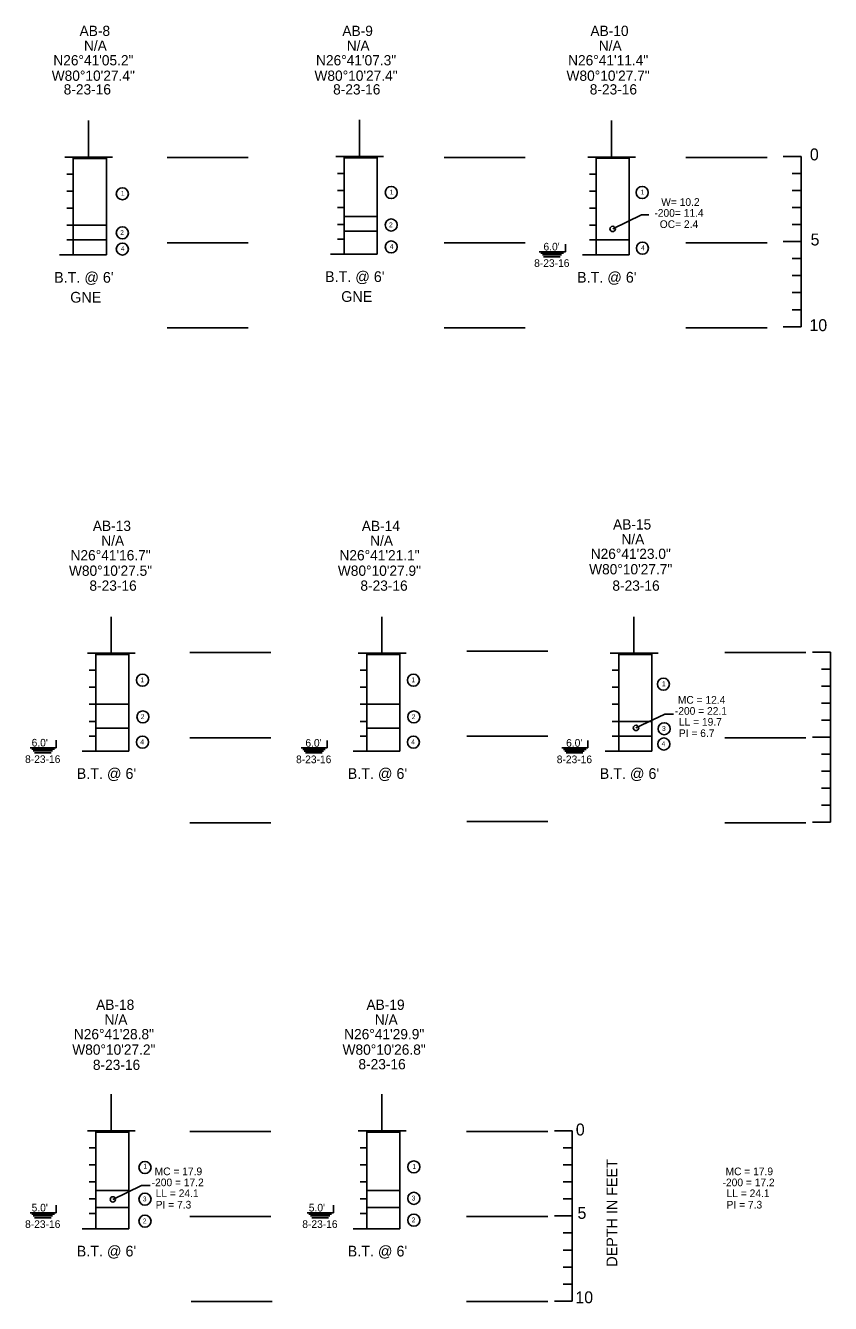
# Model space of a CAD drawing. Extents: x 0 to 331, y -72 to 117.
# Drawn here: x 93.6 to 118.94, y -21.85 to 18.38 of the extents above; entities that cross this region are included whole.
import ezdxf

# ---------------------------------------------------------------- set-up
doc = ezdxf.new("R2010")
doc.units = 0
for name, color, linetype in [('1-BORE', 7, 'Continuous'), ('1-GRID', 7, 'Continuous'), ('1-TEXT', 7, 'Continuous')]:
    doc.layers.add(name, color=color, linetype=linetype)

msp = doc.modelspace()

# ---------------------------------------------------------------- linework, layer by layer
at = {"layer": '1-BORE'}
for p, q in [((95.097, 14.2), (96.142, 14.2)), ((103.629, 14.222), (104.674, 14.222)), ((111.565, 14.202), (112.61, 14.202)), ((95.097, 12.097), (96.142, 12.097)), ((95.097, 12.097), (96.142, 12.097)), ((103.629, 12.369), (104.674, 12.369)), ((103.629, 12.369), (104.674, 12.369)), ((112.089, 11.986), (112.993, 12.426)), ((112.993, 12.426), (113.221, 12.426)), ((103.629, 11.906), (104.674, 11.906)), ((103.629, 11.906), (104.674, 11.906)), ((95.097, 11.634), (96.142, 11.634)), ((95.097, 11.634), (96.142, 11.634)), ((111.565, 11.637), (112.61, 11.637)), ((111.565, 11.637), (112.61, 11.637)), ((95.097, 11.16), (94.669, 11.16)), ((95.097, 11.16), (96.142, 11.16)), ((103.629, 11.183), (103.201, 11.183)), ((103.629, 11.183), (104.674, 11.183)), ((111.565, 11.163), (111.137, 11.163)), ((111.565, 11.163), (112.61, 11.163)), ((95.809, -1.422), (96.854, -1.422)), ((104.342, -1.422), (105.387, -1.422)), ((112.278, -1.422), (113.323, -1.422)), ((95.809, -2.989), (96.854, -2.989)), ((95.809, -2.989), (96.854, -2.989)), ((104.342, -2.989), (105.387, -2.989)), ((104.342, -2.989), (105.387, -2.989)), ((112.278, -3.525), (113.323, -3.525)), ((112.278, -3.525), (113.323, -3.525)), ((112.82, -3.734), (113.724, -3.294)), ((113.724, -3.294), (114, -3.294)), ((95.809, -3.739), (96.854, -3.739)), ((95.809, -3.739), (96.854, -3.739)), ((104.342, -3.739), (105.387, -3.739)), ((104.342, -3.739), (105.387, -3.739)), ((112.278, -3.988), (113.323, -3.988)), ((112.278, -3.988), (113.323, -3.988)), ((95.809, -4.462), (95.381, -4.462)), ((95.809, -4.462), (96.854, -4.462)), ((104.342, -4.462), (103.913, -4.462)), ((104.342, -4.462), (105.387, -4.462)), ((112.278, -4.462), (111.849, -4.462)), ((112.278, -4.462), (113.323, -4.462)), ((95.809, -16.459), (96.854, -16.459)), ((104.342, -16.459), (105.387, -16.459)), ((95.809, -18.3), (96.854, -18.3)), ((95.809, -18.3), (96.854, -18.3)), ((96.344, -18.578), (97.247, -18.139)), ((97.247, -18.139), (97.524, -18.138)), ((104.341, -18.3), (105.386, -18.3)), ((104.342, -18.3), (105.387, -18.3)), ((95.809, -18.836), (96.854, -18.836)), ((95.809, -18.836), (96.854, -18.836)), ((104.341, -18.836), (105.386, -18.836)), ((104.342, -18.836), (105.387, -18.836)), ((95.809, -19.498), (95.381, -19.498)), ((95.809, -19.498), (96.854, -19.498)), ((104.342, -19.498), (103.913, -19.498)), ((104.342, -19.498), (105.387, -19.498))]:
    msp.add_line(p, q, dxfattribs=at)
for points in [[(96.142, 14.2), (96.142, 14.241), (95.097, 14.241), (95.097, 14.2), (96.142, 14.2), (96.142, 14.2)], [(96.142, 11.16), (96.142, 14.241), (95.097, 14.241), (95.097, 11.16)], [(104.674, 14.222), (104.674, 14.263), (103.629, 14.263), (103.629, 14.222), (104.674, 14.222), (104.674, 14.222)], [(104.674, 11.183), (104.674, 14.263), (103.629, 14.263), (103.629, 11.183)], [(112.61, 14.202), (112.61, 14.243), (111.565, 14.243), (111.565, 14.202), (112.61, 14.202), (112.61, 14.202)], [(112.61, 11.163), (112.61, 14.243), (111.565, 14.243), (111.565, 11.163)], [(96.854, -4.462), (96.854, -1.381), (95.809, -1.381), (95.809, -4.462)], [(96.854, -1.422), (96.854, -1.381), (95.809, -1.381), (95.809, -1.422), (96.854, -1.422), (96.854, -1.422)], [(105.387, -4.462), (105.387, -1.381), (104.342, -1.381), (104.342, -4.462)], [(105.387, -1.422), (105.387, -1.381), (104.342, -1.381), (104.342, -1.422), (105.387, -1.422), (105.387, -1.422)], [(113.323, -4.462), (113.323, -1.381), (112.278, -1.381), (112.278, -4.462)], [(113.323, -1.422), (113.323, -1.381), (112.278, -1.381), (112.278, -1.422), (113.323, -1.422), (113.323, -1.422)], [(96.854, -19.498), (96.854, -16.418), (95.809, -16.418), (95.809, -19.498)], [(96.854, -16.459), (96.854, -16.418), (95.809, -16.418), (95.809, -16.459), (96.854, -16.459), (96.854, -16.459)], [(105.387, -19.498), (105.387, -16.418), (104.342, -16.418), (104.342, -19.498)], [(105.387, -16.459), (105.387, -16.418), (104.342, -16.418), (104.342, -16.459), (105.387, -16.459), (105.387, -16.459)]]:
    msp.add_lwpolyline(points, dxfattribs=at)
for centre, start, end in [((112.086, 11.979), 0, 180), ((112.086, 11.979), 180, 0), ((112.821, -3.732), 0, 180), ((112.821, -3.732), 180, 0), ((96.345, -18.576), 0, 180), ((96.345, -18.576), 180, 0)]:
    msp.add_arc(centre, 0.0848, start, end, dxfattribs=at)
at = {"layer": '1-GRID'}
for p, q in [((98.056, 14.223), (100.609, 14.223)), ((106.777, 14.223), (109.331, 14.223)), ((114.393, 14.223), (116.947, 14.223)), ((118.019, 14.259), (117.454, 14.259)), ((94.892, 13.705), (95.097, 13.705)), ((103.425, 13.728), (103.629, 13.728)), ((111.361, 13.708), (111.565, 13.708)), ((118.019, 13.724), (117.733, 13.724)), ((94.892, 13.169), (95.097, 13.169)), ((103.425, 13.192), (103.629, 13.192)), ((111.361, 13.172), (111.565, 13.172)), ((118.019, 13.188), (117.733, 13.188)), ((94.892, 12.633), (95.097, 12.633)), ((103.425, 12.656), (103.629, 12.656)), ((111.361, 12.636), (111.565, 12.636)), ((118.019, 12.652), (117.733, 12.652)), ((94.892, 12.097), (95.097, 12.097)), ((103.425, 12.12), (103.629, 12.12)), ((111.361, 12.1), (111.565, 12.1)), ((118.019, 12.116), (117.733, 12.116)), ((94.892, 11.634), (95.097, 11.634)), ((98.056, 11.543), (100.609, 11.543)), ((103.425, 11.657), (103.629, 11.657)), ((106.777, 11.543), (109.331, 11.543)), ((111.361, 11.637), (111.565, 11.637)), ((114.393, 11.543), (116.947, 11.543)), ((118.019, 11.58), (117.454, 11.58)), ((118.019, 11.58), (117.454, 11.58)), ((95.097, 11.16), (95.302, 11.16)), ((103.629, 11.183), (103.834, 11.183)), ((111.565, 11.163), (111.77, 11.163)), ((118.019, 11.044), (117.733, 11.044)), ((118.019, 10.508), (117.733, 10.508)), ((118.019, 9.973), (117.733, 9.973)), ((118.019, 9.437), (117.733, 9.437)), ((98.056, 8.864), (100.609, 8.864)), ((106.777, 8.864), (109.331, 8.864)), ((114.393, 8.864), (116.947, 8.864)), ((118.019, 8.901), (117.454, 8.901)), ((98.771, -1.362), (101.325, -1.362)), ((107.49, -1.317), (110.043, -1.317)), ((115.615, -1.362), (118.169, -1.362)), ((118.944, -1.344), (118.379, -1.344)), ((118.944, -1.344), (118.379, -1.344)), ((95.604, -1.917), (95.809, -1.917)), ((104.137, -1.917), (104.342, -1.917)), ((112.073, -1.917), (112.278, -1.917)), ((118.944, -1.88), (118.658, -1.88)), ((95.604, -2.453), (95.809, -2.453)), ((104.137, -2.453), (104.342, -2.453)), ((112.073, -2.453), (112.278, -2.453)), ((118.944, -2.416), (118.658, -2.416)), ((95.604, -2.989), (95.809, -2.989)), ((104.137, -2.989), (104.342, -2.989)), ((112.073, -2.989), (112.278, -2.989)), ((118.944, -2.952), (118.658, -2.952)), ((95.604, -3.525), (95.809, -3.525)), ((104.137, -3.525), (104.342, -3.525)), ((112.073, -3.525), (112.278, -3.525)), ((118.944, -3.487), (118.658, -3.487)), ((95.604, -3.988), (95.809, -3.988)), ((104.137, -3.988), (104.342, -3.988)), ((107.49, -3.996), (110.043, -3.996)), ((112.073, -3.988), (112.278, -3.988)), ((118.944, -4.023), (118.379, -4.023)), ((118.944, -4.023), (118.379, -4.023)), ((98.771, -4.042), (101.325, -4.042)), ((115.615, -4.042), (118.169, -4.042)), ((95.809, -4.462), (96.014, -4.462)), ((104.342, -4.462), (104.546, -4.462)), ((112.278, -4.462), (112.482, -4.462)), ((118.944, -4.559), (118.658, -4.559)), ((118.944, -5.095), (118.658, -5.095)), ((118.944, -5.631), (118.658, -5.631)), ((118.944, -6.167), (118.658, -6.167)), ((98.771, -6.721), (101.325, -6.721)), ((107.49, -6.675), (110.043, -6.675)), ((115.615, -6.721), (118.169, -6.721)), ((118.944, -6.703), (118.379, -6.703)), ((98.771, -16.438), (101.324, -16.438)), ((107.485, -16.439), (110.039, -16.439)), ((110.815, -16.419), (110.25, -16.419)), ((110.815, -16.419), (110.25, -16.419)), ((95.604, -16.954), (95.809, -16.954)), ((104.137, -16.954), (104.342, -16.954)), ((110.815, -16.955), (110.529, -16.955)), ((95.604, -17.489), (95.809, -17.489)), ((104.137, -17.489), (104.342, -17.489)), ((110.815, -17.491), (110.529, -17.491)), ((95.604, -18.025), (95.809, -18.025)), ((104.137, -18.025), (104.342, -18.025)), ((110.815, -18.026), (110.529, -18.026)), ((95.604, -18.561), (95.809, -18.561)), ((104.137, -18.561), (104.342, -18.561)), ((110.815, -18.562), (110.529, -18.562)), ((95.604, -19.024), (95.809, -19.024)), ((98.771, -19.117), (101.324, -19.117)), ((104.137, -19.024), (104.342, -19.024)), ((107.485, -19.118), (110.039, -19.118)), ((110.815, -19.098), (110.25, -19.098)), ((110.815, -19.098), (110.25, -19.098)), ((95.809, -19.498), (96.014, -19.498)), ((104.342, -19.498), (104.546, -19.498)), ((110.815, -19.634), (110.529, -19.634)), ((110.815, -20.17), (110.529, -20.17)), ((110.815, -20.706), (110.529, -20.706)), ((110.815, -21.242), (110.529, -21.242)), ((98.808, -21.796), (101.362, -21.796)), ((107.485, -21.796), (110.039, -21.796)), ((110.815, -21.777), (110.25, -21.777))]:
    msp.add_line(p, q, dxfattribs=at)
for points in [[(118.019, 11.58), (118.019, 14.259)], [(118.019, 8.901), (118.019, 11.58)], [(118.944, -4.023), (118.944, -1.344)], [(118.944, -6.703), (118.944, -4.023)], [(110.815, -19.098), (110.815, -16.419)], [(110.815, -21.777), (110.815, -19.098)]]:
    msp.add_lwpolyline(points, dxfattribs=at)
at = {"layer": '1-TEXT'}
for p, q in [((95.577, 15.392), (95.577, 14.241)), ((104.109, 15.414), (104.109, 14.263)), ((112.045, 15.394), (112.045, 14.243)), ((110.595, 11.262), (110.595, 11.497)), ((109.77, 11.262), (110.595, 11.262)), ((109.824, 11.213), (110.534, 11.213)), ((109.871, 11.164), (110.478, 11.164)), ((109.91, 11.105), (110.434, 11.105)), ((96.289, -0.23), (96.289, -1.381)), ((104.821, -0.23), (104.821, -1.381)), ((112.757, -0.23), (112.757, -1.381)), ((93.739, -4.356), (94.564, -4.356)), ((93.793, -4.405), (94.503, -4.405)), ((94.564, -4.356), (94.564, -4.121)), ((102.271, -4.363), (103.097, -4.363)), ((102.326, -4.412), (103.036, -4.412)), ((103.097, -4.363), (103.097, -4.127)), ((110.482, -4.363), (111.307, -4.363)), ((110.536, -4.412), (111.246, -4.412)), ((111.307, -4.363), (111.307, -4.127)), ((93.841, -4.454), (94.447, -4.454)), ((93.879, -4.513), (94.404, -4.513)), ((102.373, -4.461), (102.98, -4.461)), ((102.412, -4.52), (102.936, -4.52)), ((110.584, -4.461), (111.19, -4.461)), ((110.622, -4.52), (111.147, -4.52)), ((96.289, -15.267), (96.289, -16.418)), ((104.821, -15.267), (104.821, -16.418)), ((94.564, -18.996), (94.564, -18.76)), ((103.293, -18.996), (103.293, -18.76)), ((93.739, -18.996), (94.564, -18.996)), ((93.793, -19.045), (94.503, -19.045)), ((93.841, -19.094), (94.447, -19.094)), ((93.879, -19.153), (94.404, -19.153)), ((102.468, -18.996), (103.293, -18.996)), ((102.522, -19.045), (103.232, -19.045)), ((102.57, -19.094), (103.176, -19.094)), ((102.608, -19.153), (103.133, -19.153))]:
    msp.add_line(p, q, dxfattribs=at)
for points in [[(94.83, 14.241), (96.339, 14.241)], [(103.363, 14.263), (104.872, 14.263)], [(111.299, 14.243), (112.808, 14.243)], [(95.543, -1.381), (97.052, -1.381)], [(104.075, -1.381), (105.584, -1.381)], [(112.011, -1.381), (113.52, -1.381)], [(95.543, -16.418), (97.052, -16.418)], [(104.075, -16.418), (105.584, -16.418)]]:
    msp.add_lwpolyline(points, dxfattribs=at)
for centre in [(96.645, 13.087), (105.113, 13.127), (113.016, 13.127), (105.113, 12.103), (96.645, 11.856), (96.645, 11.346), (105.113, 11.412), (113.023, 11.373), (97.278, -2.23), (105.81, -2.23), (113.682, -2.356), (97.292, -3.385), (105.825, -3.385), (113.709, -3.757), (97.278, -4.179), (105.81, -4.179), (113.695, -4.239), (97.357, -17.571), (105.825, -17.554), (97.357, -18.57), (105.824, -18.543), (97.357, -19.262), (105.824, -19.229)]:
    msp.add_circle(centre, 0.19, dxfattribs=at)

# ---------------------------------------------------------------- texts
at = {"layer": '1-GRID'}
for s, height, p in [('0', 0.375, (118.296, 14.138)), ('5', 0.375, (118.319, 11.459)), ('10', 0.3751, (118.282, 8.762)), ('0', 0.375, (110.925, -16.563)), ('5', 0.375, (110.978, -19.189)), ('10', 0.3751, (110.911, -21.847))]:
    msp.add_text(s, height=height, dxfattribs=at).set_placement(p)
msp.add_text('DEPTH IN FEET', height=0.3376, rotation=90, dxfattribs=at).set_placement((112.23, -20.695))
at = {"layer": '1-TEXT'}
for s, height, p in [('AB-8', 0.3231, (95.298, 18.054)), ('AB-9', 0.3231, (103.573, 18.054)), ('AB-10', 0.3231, (111.385, 18.054)), ('N/A', 0.3231, (95.436, 17.588)), ('N/A', 0.3231, (103.711, 17.588)), ('N/A', 0.3231, (111.649, 17.588)), ('N26%%D41\'05.2"', 0.32313, (94.47, 17.128)), ('N26%%D41\'07.3"', 0.32313, (102.744, 17.128)), ('N26%%D41\'11.4"', 0.32313, (110.682, 17.128)), ('W80%%D10\'27.4"', 0.32313, (94.42, 16.642)), ('W80%%D10\'27.4"', 0.32313, (102.694, 16.642)), ('W80%%D10\'27.7"', 0.32313, (110.632, 16.642)), ('8-23-16', 0.3231, (94.797, 16.212)), ('8-23-16', 0.3231, (103.282, 16.212)), ('8-23-16', 0.3231, (111.364, 16.212)), ('1', 0.152, (96.599, 13.025)), ('1', 0.152, (105.067, 13.065)), ('1', 0.152, (112.97, 13.065)), ('W= 10.2', 0.2411, (113.614, 12.705)), ('-200= 11.4', 0.2411, (113.399, 12.362)), ('2', 0.152, (105.044, 12.034)), ('OC= 2.4', 0.2411, (113.568, 12.009)), ('2', 0.152, (96.576, 11.788)), ('4', 0.152, (96.599, 11.284)), ('4', 0.152, (105.067, 11.35)), ("  6.0'", 0.2411, (109.728, 11.301)), ('4', 0.152, (112.977, 11.31)), ('8-23-16', 0.2411, (109.613, 10.783)), ("B.T. @ 6'", 0.3376, (94.495, 10.285)), ("B.T. @ 6'", 0.3376, (103.027, 10.308)), ("B.T. @ 6'", 0.3376, (110.963, 10.288)), ('GNE', 0.3376, (95.004, 9.659)), ('GNE', 0.3376, (103.537, 9.682)), ('AB-15', 0.3231, (112.098, 2.515)), ('AB-13', 0.3231, (95.716, 2.469)), ('AB-14', 0.3231, (104.185, 2.466)), ('N/A', 0.3231, (95.98, 2.003)), ('N/A', 0.3231, (104.448, 2.003)), ('N/A', 0.3231, (112.361, 2.049)), ('N26%%D41\'16.7"', 0.32313, (95.013, 1.543)), ('N26%%D41\'21.1"', 0.32313, (103.482, 1.543)), ('N26%%D41\'23.0"', 0.32313, (111.394, 1.589)), ('W80%%D10\'27.5"', 0.32313, (94.963, 1.057)), ('W80%%D10\'27.9"', 0.32313, (103.431, 1.057)), ('W80%%D10\'27.7"', 0.32313, (111.344, 1.103)), ('8-23-16', 0.3231, (95.608, 0.587)), ('8-23-16', 0.3231, (104.141, 0.587)), ('8-23-16', 0.3231, (112.077, 0.587)), ('1', 0.152, (97.213, -2.293)), ('1', 0.152, (105.746, -2.293)), ('1', 0.152, (113.636, -2.419)), ('MC = 12.4', 0.2411, (114.138, -2.969)), ('-200 = 22.1', 0.24114, (114.044, -3.318)), ('2', 0.152, (97.224, -3.454)), ('2', 0.152, (105.757, -3.454)), ('LL = 19.7', 0.2411, (114.171, -3.661)), ('3', 0.152, (113.64, -3.825)), ('PI = 6.7', 0.2411, (114.171, -4.018)), (" 6.0'", 0.2411, (93.698, -4.317)), ('4', 0.152, (97.21, -4.247)), ("  6.0'", 0.2411, (102.23, -4.324)), ('4', 0.152, (105.742, -4.247)), ("  6.0'", 0.2411, (110.441, -4.324)), ('4', 0.152, (113.627, -4.307)), ('8-23-16', 0.2411, (93.582, -4.835)), ('8-23-16', 0.2411, (102.115, -4.842)), ('8-23-16', 0.2411, (110.325, -4.842)), ("B.T. @ 6'", 0.3376, (95.207, -5.337)), ("B.T. @ 6'", 0.3376, (103.74, -5.337)), ("B.T. @ 6'", 0.3376, (111.676, -5.337)), ('AB-18', 0.3231, (95.82, -12.609)), ('AB-19', 0.3231, (104.332, -12.609)), ('N/A', 0.3231, (96.084, -13.075)), ('N/A', 0.3231, (104.596, -13.076)), ('N26%%D41\'28.8"', 0.32313, (95.117, -13.535)), ('N26%%D41\'29.9"', 0.32313, (103.629, -13.535)), ('W80%%D10\'27.2"', 0.32313, (95.067, -14.021)), ('W80%%D10\'26.8"', 0.32313, (103.579, -14.022)), ('8-23-16', 0.3231, (95.717, -14.5)), ('8-23-16', 0.3231, (104.079, -14.481)), ('1', 0.152, (97.309, -17.608)), ('MC = 17.9', 0.2411, (97.662, -17.814)), ('1', 0.152, (105.779, -17.617)), ('MC = 17.9', 0.2411, (115.64, -17.814)), ('MC = 17.9', 0.2411, (115.64, -17.814)), ('-200 = 17.2', 0.24114, (97.568, -18.162)), ('-200 = 17.2', 0.24114, (115.546, -18.162)), ('-200 = 17.2', 0.24114, (115.546, -18.162)), ('3', 0.152, (97.289, -18.638)), ('LL = 24.1', 0.2411, (97.694, -18.505)), ('3', 0.152, (105.756, -18.611)), ('LL = 24.1', 0.2411, (115.673, -18.505)), ('LL = 24.1', 0.2411, (115.673, -18.505)), (" 5.0'", 0.2411, (93.698, -18.957)), ('PI = 7.3', 0.2411, (97.694, -18.863)), (" 5.0'", 0.2411, (102.427, -18.957)), ('PI = 7.3', 0.2411, (115.673, -18.863)), ('PI = 7.3', 0.2411, (115.673, -18.863)), ('8-23-16', 0.2411, (93.582, -19.475)), ('2', 0.152, (97.289, -19.331)), ('8-23-16', 0.2411, (102.311, -19.475)), ('2', 0.152, (105.756, -19.298)), ("B.T. @ 6'", 0.3376, (95.207, -20.373)), ("B.T. @ 6'", 0.3376, (103.74, -20.373))]:
    msp.add_text(s, height=height, dxfattribs=at).set_placement(p)

doc.saveas('drawing.dxf')
